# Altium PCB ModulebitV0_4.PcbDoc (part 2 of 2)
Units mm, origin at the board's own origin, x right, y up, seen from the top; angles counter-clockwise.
Board outline 60 x 54 mm, 2 copper layers (Top Layer, Bottom Layer), stack 1.671 mm thick; 125 components, 87 nets, 543 pads, 469 vias.
Unrouted connection lines stored in the file: 1.
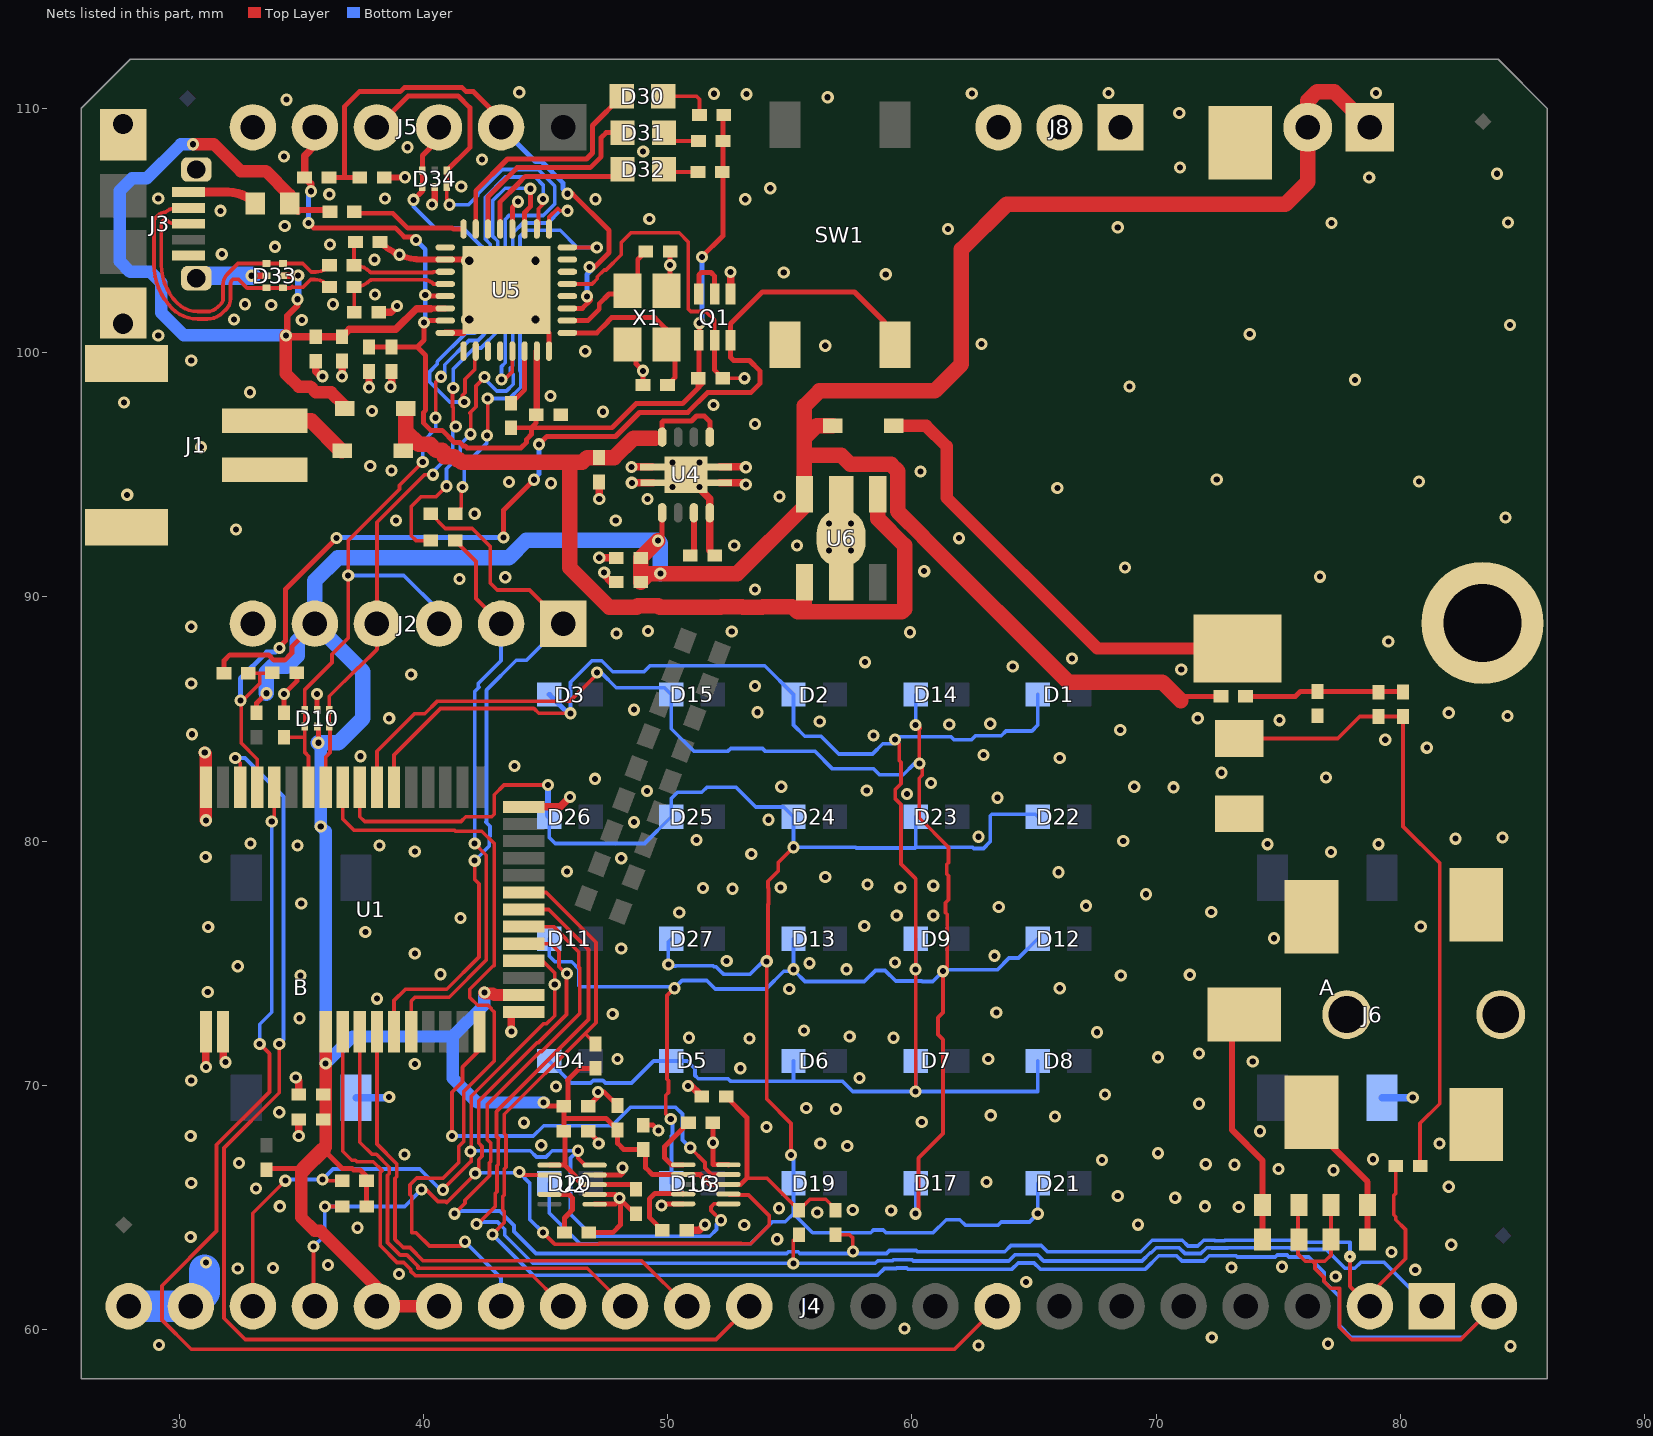
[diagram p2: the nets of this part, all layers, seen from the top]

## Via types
v1: diameter 0.5, hole 0.25, Top Layer to Bottom Layer, tented both sides, 464 vias
v2: diameter 0.66, hole 0.33, Top Layer to Bottom Layer, tented both sides, 4 vias
v3: diameter 0.5, hole 0.15, Top Layer to Bottom Layer, 1 vias

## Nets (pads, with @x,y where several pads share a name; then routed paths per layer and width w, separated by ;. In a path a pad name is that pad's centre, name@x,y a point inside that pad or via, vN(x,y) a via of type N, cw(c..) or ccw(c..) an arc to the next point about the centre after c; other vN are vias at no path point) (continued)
GND: A.2 B1.NEG B.2 C1.2 C2.2 C3.2 C4.2 C5.2 C6.2 C7.2 C8.2 C9.2 C10.2 C11.2 C12.2 C13.2 C14.2 C15.2 C16.2 C17.2 C18.2 C19.2 C20.2 C21.2 C22.2 C23.2 C24.2 C25.2 C26.2 C27.2 D10.2 D33.2 D34.2 J1.2 J1.P1 J1.P2 J2.6 J3.5 J3.H0 J3.H1 J3.H2 J3.H3 J4.21 J4.22 J5.6 J6.BARL J6.P01 J6.P02 J6.P03 J6.P04 J8.1 J8.2 J8.3 M1.BLACK M2.1 pad.2 Q1.1 R5.2 SW1.2 U1.1 U1.2 U1.13 U1.25 U1.42 U2.6 U2.7 U2.9 U3.5 U3.10 U4.4 U4.9 U5.2 U5.8 U5.16 U5.33 U6.2 X1.2 X1.4 | length 64.1
  Top Layer w0.203: R5.2@34.3,85.25 v1(34.3,86.025) 34.819,86.544 C24.2@34.819,86.893 ; D10.2@35.65,85.363 v1(35.65,86.025) ; U5.33@43.394,102.556 45.144,100.806 U5.16@45.144,100.056 ; C2.2@46.75,68.125 47.175,67.7 v1(47.175,67.625) ; C1.2@46.75,69.15 47.125,69.525 47.15,69.525 v1(47.15,69.725) 47.4,69.725 C8.2@47.95,69.175 ; C6.2@46.775,63.975 47.75,63.975 48.062,64.287 pad.2@48.062,65.337 ; U2.6@47.012,65.136 47.861,65.136 pad.2@48.062,65.337 ; U2.7@47.012,65.536 v1@47.864,65.536 ; U2.9@47.012,66.336 48.086,66.336 48.152,66.402 v1(48.152,66.628) ; C3.2@48.7,64.75 48.65,64.75 pad.2@48.062,65.337 ; X1.4@48.705,100.332 48.705,99.537 v1(48.992,99.25) C21.2@48.992,98.671 ; C9.2@49,68.375 49.4,68.375 v1(49.625,68.15) ; v1(49.752,65.078) 49.752,65.15 49.751,65.151 49.752,65.151 U3.5@50.637,65.151 ; C22.2@50.102,104.132 v1(50.102,103.575) 50.102,102.735 X1.2@50.305,102.532 ; C7.2@51.85,68.475 v1(51.85,67.653) 51.856,67.647 51.856,66.753 52.485,66.753 U3.10@52.487,66.751
  Top Layer w0.254: v1(32.963,103.143) D33.2@33.579,103.143 ; C18.2@38.225,104.525 ccw(c39.96,106.26) 39.96,103.806 U5.2@40.894,103.806 U5.33@42.144,103.806 ; C23.2@38.397,107.169 39.244,107.169 v1(39.25,107.175) ; v1(40.352,106.055) 40.462,106.165 D34.2@40.462,106.774 ; U5.8@40.894,100.806 U5.33@41.644,100.806
  Top Layer w0.305: v1(31.1,70.75) U1.1@31.1,71.699 ; U1.2@31.8,71.699 31.8,71.05 v1(31.9,70.95) ; v1(34.775,70.325) 34.9,70.2 C5.2@34.9,69.625 ; v1(34.9,67.925) C4.2@34.9,68.6 ; C25.2@35.595,99.647 35.595,99.23 35.8,99.025 v1(35.875,99.025) ; v1(36.675,99.025) C26.2@36.675,99.65 ; v1(37.775,98.575) C16.2@37.775,99.225 ; C17.2@38.175,101.65 38.675,101.65 v1(38.925,101.9) ; v1(38.65,98.6) 38.7,98.65 C19.2@38.7,99.225 ; v1(43.6,72.2) 43.599,72.999 U1.13@44.1,72.999 ; U1.25@43.8,81.399 45.599,81.399 v1(46,81.8) ; C14.2@47.193,94.699 47.193,94.007 v1(47.2,94) ; v1(47.2,91.6) 47.208,91.592 C13.2@47.895,91.592 ; v1(47.4,91) 47.4,90.9 47.698,90.602 C12.2@47.895,90.602 ; v1(48.516,95.316) U4.9@49.378,95.316 ; v1(48.534,94.666) U4.9@49.403,94.666 ; U4.9@50.749,94.991 51.724,94.016 U4.4@51.724,93.441 C15.2@51.724,91.897 ; C10.2@50.775,64.075 51.3,64.075 v1(51.525,64.3) ; v1(50.827,69.978) 50.827,70.052 50.85,70.075 50.875,70.075 C11.2@51.4,69.55 ; U4.9@52.121,94.666 53.134,94.666 v1(53.2,94.6) ; U4.9@52.121,95.316 53.184,95.316 v1(53.2,95.3) ; Q1.1@52.575,102.4 v1(52.575,103.3)
  Top Layer w0.508: v1(31.05,83.625) 31.1,83.575 U1.42@31.1,82.699 U1.42@31.1,82.199 v1(31.1,80.85)
  Bottom Layer w0.254: v1(40.352,106.055) v1@40.445,106.055
  Bottom Layer w0.305: B.2@37.25,69.5 38.575,69.5 v1(38.6,69.525) ; A.2@79.25,69.5 v1(80.5,69.5)
  Bottom Layer w0.762: J3.H3@30.709,103.041 cw(c30.954,102.796) 30.954,103.143 v1(32.963,103.143)
  Bottom Layer w1.27: J4.22@27.94,60.96 J4.21@30.48,60.96 31.05,61.53 31.05,62.45
  other v1: 84.5,59.325 62.725,59.35 29.175,59.375 77.025,59.425 72.275,59.675 59.7,60.05 64.675,61.95 77.343,62.179 39,62.275 80.6,62.45 32.4,62.5 33.85,62.525 73.075,62.55 75.15,62.575 36.1,62.65 31.1,62.75 79.625,63.175 82.075,63.475 54.483,63.703 30.475,63.8 37.3,64.175 53.137,64.287 69.25,64.3 56.125,64.8 59.15,64.875 57.578,64.903 54.559,64.973 73.375,65.025 34.125,65.05 72,65.05 48.029,65.397 70.775,65.4 68.425,65.475 33.15,65.775 81.975,65.85 30.5,66 63.05,66.05 77.25,66.525 75,66.575 73.2,66.75 72.025,66.775 32.45,66.825 67.775,66.95 78.875,66.975 39.225,67.175 70.075,67.225 57.35,67.525 44.825,67.55 56.25,67.625 81.6,67.625 30.475,67.925 74.25,68.125 54.051,68.301 44.125,68.475 60.401,68.504 65.85,68.725 63.225,68.775 34.1,68.9 56.896,69.037 55.675,69.075 71.75,69.25 67.9,69.625 45.425,69.95 30.5,70.2 57.85,70.3 52.975,70.7 39.65,70.875 73.95,70.975 47.95,71.075 63.125,71.075 70.075,71.15 71.75,71.3 53.35,71.925 50.875,71.95 59.25,71.95 57.45,72 67.575,72.175 55.575,72.25 34.925,72.75 47.75,72.925 63.453,72.979 38.1,73.55 31.175,73.825 54.975,73.95 66.05,73.975 34.975,74.5 68.55,74.5 71.375,74.525 40.7,74.55 57.325,74.75 32.4,74.875 55.803,75.004 59.303,75.029 52.415,75.098 63.378,75.304 39.65,75.4 48.1,75.6 74.825,76.025 37.625,76.275 31.191,76.479 80.825,76.5 58.05,76.525 41.525,76.85 59.375,76.95 60.875,76.95 50.475,77.075 72.25,77.1 63.553,77.304 67.125,77.35 35,77.45 69.575,77.825 52.65,78.05 51.45,78.075 54.625,78.1 59.525,78.1 60.875,78.175 58.175,78.225 56.45,78.525 66,78.725 45.875,78.75 48.1,79.3 31.09,79.35 53.425,79.475 77.15,79.55 39.65,79.575 34.85,79.825 38.2,79.825 74.55,79.875 79.1,79.875 32.925,79.9 68.65,80 51.175,80.05 82.25,80.1 84.175,80.15 62.728,80.179 48.625,80.775 54.125,80.875 63.5,81.775 59.8,81.925 49.15,82.05 58.15,82.075 70.7,82.2 54.65,82.225 69.1,82.225 60.775,82.375 47.025,82.55 76.95,82.6 72.675,82.8 43.725,83.075 66.05,83.4 37.425,83.475 62.925,83.525 81.075,83.825 79.375,84.15 58.425,84.325 30.525,84.375 68.525,84.55 61.525,84.775 63.203,84.804 56.225,84.9 75.05,84.95 38.6,85.025 71.7,85.025 84.375,85.125 81.975,85.25 53.675,85.275 48.627,85.379 53.575,86.35 30.5,86.45 39.5,86.825 71.025,87.025 64.125,87.15 58.075,87.325 66.55,87.475 79.5,88.175 47.9,88.5 59.925,88.55 52.625,88.575 49.2,88.6 30.5,88.775 53.575,90.3 41.475,90.725 43.35,90.8 76.7,90.825 60.5,91.05 68.725,91.2 56.6,91.9 57.5,91.9 52.725,92.1 55.3,92.1 61.925,92.4 32.325,92.75 56.6,93 57.5,93 38.875,93.125 47.875,93.125 84.3,93.25 42.1,93.4 49.175,94 54.575,94.1 27.875,94.175 65.95,94.45 50.2,94.5 51.3,94.5 45.225,94.65 43.5,94.7 80.75,94.725 72.475,94.8 60.35,95.125 38.7,95.175 37.825,95.35 50.2,95.5 51.3,95.5 30.9,96.125 53.575,97.075 47.35,97.575 37.9,97.6 51.875,97.85 27.75,97.95 45.2,98.225 32.9,98.375 68.91,98.603 78.13,98.882 30.5,99.675 46.625,100.05 56.45,100.275 62.85,100.35 29.15,100.7 73.825,100.75 84.475,101.125 35.025,101.325 32.25,101.35 33.775,101.95 32.7,101.975 36.3,101.975 38.025,102.375 58.925,103.2 54.75,103.275 38,103.8 39.025,104 31.75,104.025 33.925,104.325 36.175,104.425 61.475,105.05 68.425,105.125 34.325,105.175 77.175,105.3 84.4,105.325 49.251,105.461 31.7,105.8 47.05,106.275 53.175,106.275 29.15,106.3 38.425,106.3 36.15,106.475 54.2,106.725 41.55,106.8 78.715,107.163 83.947,107.315 70.968,107.569 42.4,107.9 34.3,108.025 48.997,108.229 39.35,108.4 70.942,109.804 34.4,110.35 56.55,110.45 53.225,110.575 51.892,110.592 62.45,110.6 68.05,110.625 79,110.625 43.925,110.65
  other v2: 41.877,101.355 44.594,101.356 41.877,103.755 44.594,103.756
I2C.SCL: J4.19 R2.2 U1.17 U2.2 U3.7 | length 42.4
  Top Layer w0.152: v1(35.5,63.4) 35.5,61.02 J4.19@35.56,60.96 ; v1(35.968,65.043) R2.2@36.678,65.043 ; v1(39.929,65.735) 40.113,65.735 40.602,65.246 40.905,65.246 40.952,65.2 v1@42.138,66.387 ; v1@42.263,66.511 42.263,66.961 42.404,67.102 42.404,67.498 42.263,67.639 42.263,69.366 44.637,71.74 44.695,71.74 45.856,72.901 45.856,74.327 ; v1(43.927,66.453) 43.927,66.425 44.016,66.336 U2.2@45.162,66.336 ; U1.17@44.1,75.799 U1.17@44.6,75.799 45.224,75.799 45.551,75.473 45.551,74.855 v1@45.827,74.579 ; v1(44.9,63.975) 45.35,63.525 45.352,63.525 45.38,63.496 47.17,63.496 47.198,63.525 52.998,63.525 53.002,63.521 53.398,63.521 53.679,63.802 54.154,64.277 54.154,64.673 53.311,65.516 52.522,65.516 U3.7@52.487,65.551
  Bottom Layer w0.152: v1(35.5,63.4) 35.968,63.868 v1(35.968,65.043) 39.237,65.043 v1(39.929,65.735) ; v1(42.125,66.4) 42.154,66.429 43.923,66.429 44.35,66.002 44.35,64.525 v1(44.9,63.975)
  other v1: 45.877,74.579
I2C.SDA: J4.20 R1.2 U1.16 U2.10 U3.6 | length 42.8
  Top Layer w0.152: J4.20@33.02,60.96 33.02,64.77 v1(34.35,66.1) ; v1@35.925,66.1 R1.2@36.675,66.1 ; v1(40.8,65.725) 40.8,65.752 41.927,66.879 41.954,66.879 41.958,66.883 41.958,69.558 44.921,72.521 45.045,72.521 45.377,72.853 v1(45.377,74.129) 45.377,74.598 44.876,75.099 U1.16@44.6,75.099 U1.16@44.1,75.099 ; v1(46.325,67.325) 46.325,67.025 46.614,66.736 U2.10@47.012,66.736 ; v1(52.178,64.478) 51.775,64.881 51.775,65.025 51.901,65.151 U3.6@52.487,65.151
  Bottom Layer w0.152: v1(34.35,66.1) 34.4,66.15 v1(35.875,66.15) 36.298,66.573 39.85,66.573 40.698,65.725 v1(40.8,65.725) ; v1(41.925,67.3) 41.95,67.325 44.373,67.325 44.627,67.071 45.023,67.071 45.277,67.325 v1(46.325,67.325) 46.025,67.025 46.025,64.725 46.929,63.821 51.723,63.821 52.004,64.102 52.004,64.304 v1(52.178,64.478) ; v1@45.377,73.973 v1(45.377,74.129)
IF_NRST: C23.1 J5.2 R22.2 U5.19 | length 23
  Top Layer w0.203: R22.2@36.136,107.163 36.775,107.163 ; C23.1@37.391,107.163 36.775,107.163 ; J5.2@43.18,109.22 43.18,109.545 42.05,110.675 41.753,110.675 41.572,110.856 39.233,110.856 39.052,110.675 37.375,110.675 36.775,110.075 36.775,107.163 ; v1@45.8,106.5 v1(45.9,106.5) 46.1,106.5 47.604,104.996 47.604,104.091 47.013,103.5 v1(46.8,103.5) ; U5.19@45.894,101.806 46.506,101.806 46.844,102.144 46.844,102.156 v1(46.7,102.3)
  Bottom Layer w0.203: J5.2@43.18,109.22 44.582,107.818 44.84,107.818 45.711,106.947 45.711,106.689 v1(45.9,106.5) ; v1(46.7,102.3) 46.7,103.2 47,103.5 v1(46.8,103.5)
IF_TDO: U5.12
LED_COM_GREEN: D30.K U5.31 | length 9.8
  Top Layer w0.203: U5.31@42.144,105.056 42.144,106.619 43.444,107.919 46.678,107.919 46.924,108.165 46.924,109.293 D30.K@48.121,110.49
LED_DAP_BLUE: D31.K U5.30 | length 8.4
  Top Layer w0.203: U5.30@42.644,105.056 42.644,106.369 43.839,107.564 46.826,107.564 47.28,108.018 47.28,108.798 47.481,109 D31.K@48.15,109
LED_PWR_RED: D32.K U5.29 | length 6.7
  Top Layer w0.203: U5.29@43.144,105.056 43.144,106.169 43.875,106.9 43.875,106.913 44.17,107.208 47.858,107.208 D32.K@48.15,107.5
MAG_INT1: U1.12 U3.9 | length 18
  Top Layer w0.152: v1(41.175,67.925) 41.175,69.719 41.605,70.149 41.605,70.748 42.282,71.426 42.3,71.426 U1.12@42.3,71.699 ; v1(50.925,67.45) 51.525,66.85 51.525,66.616 51.79,66.351 U3.9@52.487,66.351
  Bottom Layer w0.152: v1(41.175,67.925) 44.5,67.925 44.925,68.35 47.725,68.35 48.482,69.107 50.326,69.107 50.606,68.827 50.606,67.769 v1(50.925,67.45)
MISO: J4.14 U1.5 | length 19.6
  Top Layer w0.152: U1.5@37.4,71.699 37.4,67.675 37.895,67.18 38.076,67.18 38.607,66.649 38.607,66.383 38.536,66.312 38.536,63.571 39.049,63.058 39.324,63.058 39.783,62.599 39.783,62.527 39.799,62.512 46.708,62.512 J4.14@48.26,60.96
MOSI: J4.15 U1.4 | length 17.6
  Top Layer w0.152: U1.4@36.7,71.699 36.7,67.3 37.066,66.934 37.217,66.934 37.276,66.875 37.95,66.875 38.302,66.523 38.302,66.51 38.231,66.438 38.231,63.445 38.923,62.754 39.198,62.754 39.479,62.473 39.479,62.401 39.672,62.207 44.473,62.207 J4.15@45.465,61.215
NC1: U5.9
NC2: U5.1
NC5: U5.11
NetB1_POS1: B1.POS1 D28.2 | length 19.1
  Top Layer w0.508: D28.2@59.25,97 60.579,97 61.417,96.162 61.417,94.056 67.589,87.884 B1.POS1@73.33,87.884
NetC6_1: C6.1 U2.4 | length 2.6
  Top Layer w0.203: U2.4@45.162,65.536 45.964,65.536 46.1,65.4 46.1,64.9 45.775,64.575 C6.1@45.775,63.975
NetC7_1: C7.1 U3.1 | length 2.7
  Top Layer w0.203: U3.1@50.637,66.751 50.149,66.751 49.875,67.025 49.875,67.5 C7.1@50.85,68.475
NetC10_1: C10.1 U3.4 | length 3
  Top Layer w0.203: C10.1@49.775,64.075 49.248,64.602 49.248,65.348 49.482,65.582 50.606,65.582 U3.4@50.637,65.551
NetC27_1: C27.1 R28.1 R29.1 R37.2 | length 6.5
  Top Layer w0.203: R37.2@73.65,85.925 75.7,85.925 75.9,86.125 C27.1@76.6,86.125 80.075,86.125 R29.1@80.1,86.1
NetD30_A: D30.A R15.2 | length 2.2
  Top Layer w0.152: D30.A@49.821,110.49 51.181,110.49 51.3,110.371 R15.2@51.3,109.725
NetD31_A: D31.A R16.2 | length 1.1
  Top Layer w0.152: D31.A@50.189,108.661 R16.2@51.265,108.661
NetD32_A: D32.A R17.2 | length 1.3
  Top Layer w0.152: D32.A@49.959,107.391 R17.2@51.24,107.391
NetJ6_RING: J6.RING R31.1 R32.1 | length 5.6
  Top Layer w0.254: J6.RING@76.6,68.5 76.6,68.1 78.65,66.05 R31.1@78.65,63.7
NetJ6_TIP: J6.TIP R33.1 R34.1 | length 9.7
  Top Layer w0.254: J6.TIP@73.1,72.9 73.1,68.175 74.35,66.925 R34.1@74.35,65.1 R33.1@74.35,63.7
NetM1_RED: M1.RED R28.2 R29.2 R30.2 | length 26.4
  Top Layer w0.152: M1.RED@73.4,84.2 77.425,84.2 78.325,85.1 R29.2@80.1,85.1 80.1,80.6 81.6,79.1 81.6,69.25 80.8,68.45 R30.2@80.8,66.7
NetQ1_2: Q1.2 Q1.3 | length 2.3
  Top Layer w0.203: Q1.3@51.275,102.375 Q1.3@51.275,102.4 51.275,102.425 51.275,103.175 51.375,103.275 51.775,103.275 51.925,103.125 Q1.2@51.925,102.4 Q1.2@51.925,102.375
NR: C15.1 U4.3 | length 1.6
  Top Layer w0.254: C15.1@51.074,91.841 U4.3@51.074,93.441
NRES_FB_BL: R21.2 U5.14 | length 2.4
  Top Layer w0.203: R21.2@43.586,97.92 44.144,98.478 U5.14@44.144,100.056
P0: J4.0 R26.2 R31.2 R32.2 R33.2 R34.2 U1.20 | length 78.8
  Top Layer w0.152: v1(42.825,63.9) 43.315,64.39 43.315,64.839 43.249,64.905 43.249,65.45 43.315,65.517 43.315,66.576 43.384,66.645 43.384,67.949 43.315,68.019 43.315,68.815 46.611,72.111 ; U1.20@44.6,77.899 45.026,77.899 47.067,75.858 47.067,72.567 46.611,72.111 ; R26.2@47.041,71.696 46.626,72.111 46.611,72.111 ; 75.8,64.6 75.8,63.1 76.1,62.8 76.4,62.8 ; R32.2@77.15,65.1 R31.2@77.15,63.7 77.15,63.05 76.9,62.8 76.4,62.8 ; 77.499,61.701 77.145,61.701 76.864,61.981 76.864,62.136 76.5,62.5 76.5,62.7 76.4,62.8 ; 77.5,61.7 77.5,60.1 78,59.6 82.46,59.6 J4.0@83.82,60.96
  Bottom Layer w0.152: v1(42.825,63.9) 44.491,62.234 58.601,62.234 58.873,62.507 59.351,62.507 59.374,62.53 59.783,62.53 59.833,62.48 64.097,62.48 64.351,62.733 64.999,62.733 65.253,62.48 69.555,62.48 70.104,63.029 70.832,63.029 71.049,62.812 71.951,62.812 72.168,63.029 73.273,63.029 73.327,62.975 74.873,62.975 74.952,63.054 75.348,63.054 75.427,62.975 76.242,62.975 76.864,62.353 76.864,61.981 77.495,61.35 77.495,60.173 77.978,59.69 82.55,59.69 J4.0@83.82,60.96 J4.0@83.715,60.96
P0.16: J4.16 U1.34 | length 32.6
  Top Layer w0.152: U1.34@36.7,81.999 36.7,80.9 37.158,80.442 41.273,80.442 41.308,80.407 42.393,80.407 42.9,79.9 42.9,74.9 42.883,74.917 41.9,73.933 41.9,73.6 42.222,73.278 42.645,73.278 42.779,73.144 42.779,73.121 42.9,73 42.9,71 41.654,69.754 41.654,67.705 41.446,67.498 41.446,66.846 40.804,66.204 40.137,66.204 40.127,66.214 39.731,66.214 39.45,65.933 39.45,65.537 39.521,65.466 39.521,63.973 39.703,63.973 40.25,63.426 41.526,63.426 v1(41.7,63.6)
  Bottom Layer w0.152: v1(41.7,63.6) 43.18,62.12 J4.16@43.18,60.96
P0.18: J4.8 U1.38 | length 59.5
  Top Layer w0.152: v1(33.3,71.7) 33.7,71.3 33.7,69.731 31.537,67.568 31.537,64.037 29.3,61.8 29.3,60.4 30.5,59.2 61.74,59.2 J4.8@63.5,60.96 ; v1(33.795,80.805) 33.9,80.91 U1.38@33.9,82.199
  Bottom Layer w0.152: v1(33.3,71.7) 33.3,72.5 33.795,72.995 v1(33.795,80.805)
P0.20: J4.12 U1.40 | length 48.7
  Top Layer w0.152: v1(32.3,83.4) 32.5,83.2 U1.40@32.5,82.699 U1.40@32.5,82.199 ; v1(34.1,71.7) 34.1,69.7 31.841,67.441 31.841,60.472 32.713,59.6 51.98,59.6 J4.12@53.34,60.96
  Bottom Layer w0.152: v1(32.3,83.4) 32.7,83.4 34.274,81.826 34.274,71.874 v1(34.1,71.7)
P1: J4.1 R25.2 U1.19 | length 59.2
  Top Layer w0.152: v1@42.225,64.325 42.942,65.042 42.942,65.574 43.01,65.643 43.01,66.702 43.064,66.756 43.064,67.808 43.079,67.823 42.995,67.907 ; 42.998,67.91 42.995,67.912 42.995,68.926 46.762,72.693 46.762,75.566 45.128,77.199 U1.19@44.6,77.199 ; v1(55.143,62.713) 55.143,63.66 R25.2@55.372,63.889
  Bottom Layer w0.152: v1(42.175,64.325) 42.254,64.404 43.034,64.404 43.329,64.109 43.329,63.863 44.475,62.717 58.498,62.717 58.598,62.817 59.194,62.817 59.237,62.86 60.009,62.86 60.059,62.81 63.96,62.81 64.214,63.064 65.136,63.064 65.39,62.81 69.418,62.81 69.758,63.15 69.794,63.15 70.002,63.358 70.934,63.358 71.176,63.117 71.824,63.117 72.066,63.358 72.259,63.358 72.276,63.342 72.924,63.342 72.941,63.358 75.474,63.358 75.553,63.28 76.963,63.28 77.729,62.513 78.125,62.513 78.367,62.755 79.332,62.755 81.127,60.96 J4.1@81.28,60.96
P2: J4.2 R24.2 R30.1 U1.18 | length 64.8
  Top Layer w0.152: v1(41.275,64.75) 41.704,65.179 41.704,65.302 42.705,66.303 42.705,66.829 42.759,66.883 42.759,67.646 42.619,67.786 42.619,69.219 44.785,71.385 44.842,71.385 46.407,72.949 46.407,74.798 46.356,74.849 46.356,75.469 45.326,76.499 U1.18@44.6,76.499 U1.18@44.1,76.499 ; R24.2@56.871,63.889 57.447,63.889 57.582,63.754 v1(57.582,63.195) ; v3(77.927,62.992) 77.927,61.773 J4.2@78.74,60.96 ; J4.2@78.74,61.1 78.74,61.44 80.2,62.9 80.2,64.1 79.8,64.5 79.8,64.627 79.721,64.705 79.721,65.495 79.8,65.573 R30.1@79.8,66.7
  Bottom Layer w0.152: v1(41.275,64.75) 41.379,64.854 43.122,64.854 43.71,64.267 43.71,64.021 44.609,63.121 54.875,63.121 54.945,63.191 55.342,63.191 55.411,63.121 58.96,63.121 59.079,63.241 60.167,63.241 60.217,63.191 63.802,63.191 64.056,63.445 65.294,63.445 65.548,63.191 69.368,63.191 69.84,63.663 71.06,63.663 71.302,63.421 71.698,63.421 71.94,63.663 72.385,63.663 72.402,63.646 72.798,63.646 72.815,63.663 75.601,63.663 75.679,63.585 77.927,63.585 v3(77.927,62.992)
PRE_TGT_NRST: Q1.5 R27.2 U5.21 | length 13.8
  Top Layer w0.152: U5.21@45.894,102.806 46.906,102.806 47.121,103.021 47.121,103.098 47.402,103.379 47.479,103.379 48.1,104 48.1,104.5 48.5,104.9 50.475,104.9 50.846,104.529 50.846,101.779 50.946,101.679 51.571,101.679 51.925,101.325 Q1.5@51.925,100.5 ; R27.2@52.25,98.95 v1(53.15,98.95)
  Top Layer w0.203: Q1.5@51.925,100.5 51.925,99.275 R27.2@52.25,98.95
  Bottom Layer w0.152: v1@53.15,98.85 v1(53.15,98.95)
PRE_TGT_RXD: R36.2 U5.25 | length 20.7
  Top Layer w0.152: R36.2@40.3,92.3 39.7,92.3 39.5,92.5 39.5,93.7 39.9,94.1 40.523,94.1 v1(40.948,94.525) ; v1(41.935,96.658) 41.935,97.488 41.9,97.523 42.154,97.777 42.154,98.63 42.5,98.977 v1(42.5,99) ; U5.25@45.144,105.056 45.144,105.544 45.5,105.9 45.6,105.8 v1(45.9,105.8)
  Bottom Layer w0.152: v1(40.948,94.525) 40.948,95.239 41.2,95.492 ; 41.2,95.492 41.51,95.802 41.51,96.233 v1(41.935,96.658) ; v1@42.6,98.823 43.002,98.421 43.398,98.421 43.679,98.702 43.679,99.098 43.566,99.211 43.566,99.364 43.655,99.454 43.655,104.886 44.074,105.305 45.1,105.305 45.595,105.8 v1(45.9,105.8)
PRE_TGT_TXD: R35.2 U5.24 | length 18.1
  Top Layer w0.152: R35.2@41.3,93.4 41.55,93.65 v1@41.55,94.55 ; v1@42.632,96.6 v1(42.632,98.114) ; U5.24@45.894,104.306 45.9,104.3 v1(47.1,104.3)
  Bottom Layer w0.152: v1(41.6,94.5) 41.679,94.578 41.679,95.298 41.638,95.338 42.6,96.3 v1(42.6,96.6) ; v1(42.632,98.114) 42.486,98.114 42.484,98.116 43.524,98.116 43.983,98.575 43.983,99.224 43.96,99.248 43.96,104.76 44.2,105 45.6,105 46.3,104.3 v1(47.1,104.3)
ROW1: D1.A D2.A D3.A D4.A D5.A D6.A D7.A D8.A D9.A U1.31 | length 76.6
  Top Layer w0.152: U1.31@38.8,82.199 38.8,83.525 40.7,85.425 44.523,85.425 44.719,85.229 v1(46.027,85.229) ; v1(59.303,84.154) 59.477,83.98 59.477,83.304 59.55,83.23 59.55,82.352 59.321,82.123 59.321,81.727 59.55,81.498 59.55,79.064 60.15,78.464 v1(60.15,74.75) v1(60.15,69.75)
  Bottom Layer w0.152: D4.A@45.15,71 46.054,70.096 46.845,70.096 46.952,70.204 47.348,70.204 47.455,70.096 48.521,70.096 49.425,71 D5.A@50.15,71 50.8,71 51.121,70.679 51.121,70.405 51.255,70.271 52.474,70.271 52.57,70.175 55.15,70.175 ; v1(46.027,85.229) 46.027,86.506 46.904,87.383 47.301,87.383 47.754,86.929 49.029,86.929 49.275,87.175 53.975,87.175 D2.A@55.15,86 55.15,84.75 55.607,84.293 56.277,84.293 57.004,83.566 58.385,83.566 58.8,83.981 v1@59.206,83.981 ; D6.A@55.15,71 55.15,70.175 ; v1(59.303,84.154) 59.416,84.267 61.595,84.267 61.708,84.154 62.446,84.154 62.601,84.308 63.651,84.308 63.851,84.508 64.908,84.508 65.15,84.75 D1.A@65.15,86 ; D7.A@60.15,71 v1(60.15,69.75) ; v1(60.15,74.75) D9.A@60.15,76 ; D8.A@65.15,71 65.15,69.75 v1(60.15,69.75) ; 55.15,70.175 57.15,70.175 57.575,69.75 v1(60.15,69.75)
  Bottom Layer w0.203: D3.A@45.186,86 D3.A@45.15,86 45.921,85.229 v1(46.027,85.229)
ROW2: D11.A D12.A D13.A D14.A D15.A D16.A D17.A U1.32 | length 85.2
  Top Layer w0.152: U1.32@38.1,82.199 U1.32@38.1,82.699 38.1,83.675 39.638,85.212 40.056,85.212 40.574,85.73 46.005,85.73 v1@47.102,86.827 ; v1(50.127,68.628) 49.925,68.831 49.925,69.598 50.031,69.704 50.031,70.196 49.976,70.251 49.976,73.676 v1(50.275,73.975) ; v1(60.15,64.75) 60.266,64.866 60.266,67.022 61.27,68.027 61.27,69.27 61.275,69.275 61.275,71.874 61.067,72.082 61.067,72.774 61.275,72.983 v1(61.275,74.675) 61.449,74.849 61.449,77.006 61.374,77.081 61.374,77.477 61.5,77.603 61.5,78.573 61.421,78.652 61.421,79.048 61.5,79.127 61.5,79.75 60.296,80.954 60.296,82.573 60.425,82.702 60.425,83.2 60.303,83.322 60.303,84.597 v1@60.275,84.625
  Top Layer w0.254: v1(60.15,84.75) v1@60.275,84.625
  Bottom Layer w0.152: D11.A@45.15,76 45.15,75.3 45.393,75.057 46.075,75.057 46.356,74.777 46.356,74.094 46.415,74.035 50.215,74.035 v1(50.275,73.975) 50.592,74.292 51.603,74.292 51.95,73.945 54.028,73.945 54.754,74.671 55.204,74.671 55.625,74.25 58.047,74.25 58.505,74.707 58.901,74.707 59.337,74.271 60.405,74.271 60.426,74.25 60.85,74.25 v1(61.275,74.675) 61.337,74.737 63.498,74.737 63.974,75.213 64.363,75.213 D12.A@65.15,76 ; v1(47.102,86.904) 47.269,86.904 47.898,86.275 49.875,86.275 D15.A@50.15,86 50.15,84.6 51.067,83.683 52.474,83.683 52.578,83.787 53.883,83.787 53.987,83.683 56.024,83.683 56.751,82.956 58.436,82.956 58.674,82.719 59.644,82.719 60.104,83.179 v1(60.303,83.179) ; v1(50.127,68.628) 50.127,68.685 50.201,68.758 50.201,67.886 50.156,67.931 50.156,66.006 D16.A@50.15,66 ; v1(55.15,74.75) D13.A@55.15,76 ; v1(60.15,64.75) D17.A@60.15,66 ; v1(60.15,84.75) D14.A@60.15,86
ROW3: D19.A D20.A D21.A D22.A D23.A D24.A D25.A D26.A D27.A U1.33 | length 84.6
  Top Layer w0.152: U1.33@37.4,82.199 U1.33@37.4,81.999 37.4,81 37.6,80.8 41.539,80.8 41.739,81 42.8,81 42.9,81.1 42.9,81.9 43.3,82.3 v1(45.1,82.3) ; v1(55.05,67.15) 55.05,68.445 54.053,69.442 v1(54.053,75.079) 54.104,75.13 54.104,77.405 54.124,77.426 54.124,78.074 54.104,78.095 54.104,78.354 54.525,78.775 54.525,79.125 v1(55.15,79.75)
  Top Layer w0.254: U1.33@37.4,82.199 U1.33@37.4,82.699
  Bottom Layer w0.152: D20.A@45.15,66 45.15,64.775 46.408,63.517 53.393,63.517 54.291,64.414 54.814,64.414 55.15,64.75 ; D26.A@45.15,81 45.15,80.148 45.398,79.9 49.05,79.9 D25.A@50.15,81 50.15,81.748 50.402,82 50.998,82 51.002,81.996 51.398,81.996 51.605,82.204 52.801,82.204 53.605,81.4 54.75,81.4 D24.A@55.15,81 v1(55.15,79.75) 57.698,79.75 57.727,79.721 60.121,79.721 60.15,79.75 ; D27.A@50.15,76 50.027,75.877 v1(50.027,74.954) 50.027,74.91 50.059,74.879 50.317,74.879 50.339,74.901 51.856,74.901 51.898,74.86 51.976,74.86 52.155,74.681 52.281,74.555 53.379,74.555 53.999,75.175 54.1,75.175 54.053,75.128 v1(54.053,75.079) ; v1(55.05,67.15) 55.15,67.05 D19.A@55.15,66 55.15,64.75 ; D23.A@60.15,81 60.15,79.75 ; D21.A@65.15,66 v1(65.15,64.75) 64.81,64.41 63.656,64.41 63.518,64.271 62.193,64.271 61.961,64.504 61.402,64.504 60.865,63.967 58.935,63.967 58.823,64.079 58.427,64.079 58.315,63.967 55.933,63.967 55.15,64.75 ; D22.A@65.15,81 65.05,81.1 63.273,81.1 63.207,81.033 63.207,79.981 62.926,79.7 62.53,79.7 62.48,79.75 60.15,79.75
  Bottom Layer w0.254: v1(45.1,82.3) 45.1,81.05 D26.A@45.15,81
SCK: J4.13 U1.6 | length 21.5
  Top Layer w0.152: U1.6@38.1,71.699 38.1,67.6 38.912,66.788 38.912,66.257 38.841,66.186 38.841,63.698 39.175,63.363 39.451,63.363 39.997,62.817 48.943,62.817 J4.13@50.8,60.96
SLEEP_NREQ: U5.20
SWCLK: D10.3 D10.4 J2.3 R5.1 U1.36 U5.26 | length 38.1
  Top Layer w0.152: R5.1@34.3,84.25 35.125,84.25 ; U1.36@35.3,82.199 U1.36@35.3,82.699 35.3,83.475 35.15,83.625 D10.4@35.15,84.688 D10.3@35.15,85.363 35.15,86.202 36.262,87.313 36.262,87.648 36.921,88.308 v1(36.921,90.875) 36.928,90.881 36.928,92.309 39.019,94.4 39.019,94.567 v1(39.975,95.523) ; v1(40.502,97.33) 40.502,98.78 v1(40.727,99.005) ; U5.26@44.644,105.056 44.709,105.121 44.709,105.884 44.902,106.077 v1(44.902,106.28)
  Bottom Layer w0.152: v1(36.921,90.875) 39.2,90.875 40.64,89.435 J2.3@40.64,88.9 ; v1(39.975,95.523) 39.975,96.348 40.502,96.875 v1(40.502,97.33) ; v1@40.875,98.925 40.875,99.5 41.867,100.492 42.235,100.492 42.74,100.997 42.74,102.031 42.708,102.064 42.708,103.108 42.74,103.141 42.74,104.431 42.531,104.641 42.531,106.356 43.358,107.183 44.577,107.183 44.902,106.858 v1(44.902,106.28)
SWD_DIO: D34.3 D34.4 J5.4 U5.13 | length 25.2
  Top Layer w0.152: D34.3@40.962,106.774 40.962,106.163 v1(41.075,106.05) ; v1(43.2,98.9) 43.325,98.9 43.644,99.219 U5.13@43.644,100.056
  Top Layer w0.203: J5.4@38.1,109.22 39.38,110.5 41.425,110.5 41.9,110.025 41.9,108.387 D34.4@40.962,107.449 D34.3@40.962,106.774
  Bottom Layer w0.152: v1(41.075,106.05) 41.85,106.05 42.226,106.426 42.226,106.482 43.231,107.487 44.703,107.487 45.381,106.81 45.381,106.082 44.908,105.61 43.51,105.61 43.35,105.45 43.35,99.58 43.2,99.43 v1(43.2,98.9)
SWD_TCLK: D34.1 D34.6 J5.3 U5.10 | length 18
  Top Layer w0.152: v1(41.675,97.975) 41.598,98.052 41.598,98.247 41.704,98.352 41.704,98.904 42.104,99.304 42.104,100.016 U5.10@42.144,100.056
  Top Layer w0.203: v1(39.6,106.25) 39.962,106.612 D34.1@39.962,106.774 D34.6@39.962,107.449 39.962,108.062 40.64,108.74 J5.3@40.64,109.22
  Bottom Layer w0.152: v1(39.6,106.25) 39.6,105.975 40.475,105.1 41.619,105.1 42.404,104.315 42.425,104.315 42.436,104.305 42.436,103.268 42.403,103.235 42.403,101.792 42.436,101.759 42.436,101.124 42.108,100.796 41.74,100.796 40.57,99.626 40.57,99.525 40.248,99.203 40.248,98.807 41.08,97.975 v1(41.675,97.975)
SWDIO_RST: D10.1 D10.6 J2.4 U1.35 U5.27 | length 30.9
  Top Layer w0.152: U1.35@36,82.199 U1.35@36,82.699 36,83.446 36.179,83.625 36.179,84.659 D10.6@36.15,84.688 D10.1@36.15,85.363 36.15,85.925 37.321,87.096 37.348,87.096 38.1,87.848 J2.4@38.1,88.9 38.1,93.05 40.05,95 v1(40.4,95) ; v1(41.225,98.55) 41.196,98.521 41.196,97.777 41.225,97.748 41.225,96.825 41.324,96.924 v1(41.324,96.97)
  Top Layer w0.203: U5.27@44.144,105.056 44.144,105.731 44.379,105.966 v1(44.379,106.704)
  Bottom Layer w0.152: v1@40.498,95.221 41.206,95.929 v1@41.206,96.794 ; v1(41.225,98.55) 41.225,99.325 42.087,100.187 42.361,100.187 43.045,100.871 43.045,102.157 43.012,102.19 43.012,102.982 43.045,103.015 43.045,104.557 42.835,104.767 42.835,106.21 43.35,106.725 44.358,106.725 v1(44.379,106.704)
TARGET_SWD.NRST: C24.1 Q1.6 R23.2 SW1.1 U1.39 | length 47.3
  Top Layer w0.152: v1@32.55,85.702 32.55,84.002 33.2,83.352 U1.39@33.2,82.699 U1.39@33.2,82.199 ; v1@32.555,85.707 33.3,86.452 33.3,86.868 ; R23.2@32.837,86.868 33.3,86.868 ; C24.1@33.819,86.893 33.793,86.868 33.3,86.868
  Top Layer w0.203: v1(34.112,87.909) 34.087,87.909 34.016,87.981 34.138,87.981 34.356,88.199 34.356,90.312 v1(36.449,92.405) ; v1(43.282,92.431) 43.282,93.548 v1(44.526,94.793) ; v1(44.729,96.241) 45.053,96.564 47.867,96.564 48.847,97.544 50.093,97.544 50.099,97.55 50.749,97.55 ; 50.753,97.55 50.749,97.55 ; SW1.1@58.875,100.825 58.875,101.25 57.65,102.475 53.875,102.475 52.575,101.175 Q1.6@52.575,100.5 52.575,99.8 52.7,99.675 53.35,99.675 53.775,99.25 53.775,98.725 53.404,98.354 51.629,98.354 50.825,97.55 50.749,97.55
  Bottom Layer w0.203: v1(32.512,85.75) 32.512,86.66 33.587,87.736 33.938,87.736 v1(34.112,87.909) ; v1(36.449,92.405) 36.474,92.431 v1(43.282,92.431) ; v1(44.526,94.793) 44.526,94.818 44.729,95.021 v1(44.729,96.241)
TGT_NRESET_X: U5.22
TGT_RXD: J2.2 R36.1 U1.8 | length 23.4
  Top Layer w0.152: U1.8@39.5,72.399 39.5,73.45 39.659,73.609 41.059,73.609 42.579,75.129 42.579,79.421 v1(42.1,79.9) ; R36.1@41.3,92.3 42.154,91.446 42.154,89.926 J2.2@43.18,88.9
  Bottom Layer w0.152: v1(42.1,79.9) 42.1,86.127 42.275,86.302 42.25,86.327 42.25,86.45 43.18,87.38 J2.2@43.18,88.9
TGT_SWO: U5.28 | length 1.2
  Top Layer w0.203: U5.28@43.644,105.056 43.644,105.944 v1(43.875,106.175)
TGT_TXD: J2.1 R35.1 U1.7 | length 29.3
  Top Layer w0.152: U1.7@38.8,72.199 38.8,73.475 39.264,73.939 40.958,73.939 42.274,75.255 42.274,78.256 42.1,78.43 v1(42.1,79.2) ; R35.1@40.3,93.4 40.9,92.8 42,92.8 42.74,92.06 42.74,90.56 43.025,90.275 44.345,90.275 J2.1@45.72,88.9
  Bottom Layer w0.152: v1(42.1,79.2) 42.7,79.8 42.7,80.181 42.729,80.209 42.729,80.606 42.555,80.78 42.58,80.805 42.58,86.18 43.8,87.4 44.22,87.4 J2.1@45.72,88.9
USB_D_N: C17.1 R20.2 U5.4 | length 4.9
  Top Layer w0.152: R20.2@37.16,102.676 ccw(c37.16,103.585) 37.802,102.942 cw(c37.877,102.868) 37.877,102.973 40.015,102.973 cw(c40.015,102.403) 40.418,102.806 U5.4@40.894,102.806 ; C17.1@37.175,101.65 R20.2@37.175,102.662
USB_D_P: C18.1 R19.2 U5.3 | length 4.7
  Top Layer w0.152: C18.1@37.16,104.46 R19.2@37.16,103.575 cw(c37.16,102.667) 37.802,103.309 ccw(c37.877,103.383) 37.877,103.278 40.39,103.278 cw(c40.458,103.21) 40.458,103.306 U5.3@40.894,103.306
USB_N: D33.3 D33.4 J3.2 R20.1 | length 13.5
  Top Layer w0.152: J3.2@30.384,105.916 29.876,105.916 ccw(c29.876,105.327) 29.46,105.744 29.45,105.744 ccw(c29.45,105.292) 29.13,105.611 29.059,105.541 ccw(c29.275,105.325) 28.97,105.325 28.97,103.594 ccw(c31.494,103.594) 29.709,101.809 ccw(c30.77,102.87) 30.77,101.37 31.15,101.37 ccw(c31.15,102.279) 31.792,101.636 31.941,101.784 ccw(c31.544,102.181) 32.105,102.181 32.105,102.77 cw(c32.43,102.77) 32.2,103 32.429,103 32.786,102.643 D33.3@33.579,102.643 D33.4@34.254,102.643 34.566,102.643 34.636,102.713 34.677,102.671 35.073,102.671 35.392,102.991 35.55,102.991 cw(c35.55,102.276) 36.055,102.781 R20.1@36.16,102.676
USB_P: D33.1 D33.6 J3.3 R19.1 | length 12.5
  Top Layer w0.152: J3.3@30.384,105.266 29.876,105.266 cw(c29.876,105.856) 29.46,105.439 29.45,105.439 ccw(c29.45,105.292) 29.346,105.396 29.275,105.325 29.275,103.594 ccw(c31.494,103.594) 29.925,102.025 ccw(c30.77,102.87) 30.77,101.675 31.15,101.675 ccw(c31.15,102.279) 31.577,101.852 31.725,102 ccw(c31.544,102.181) 31.8,102.181 31.8,102.77 cw(c32.43,102.77) 31.984,103.215 ; 31.984,103.216 32.412,103.643 D33.6@34.254,103.643 35.059,103.643 35.406,103.295 35.593,103.295 ccw(c35.593,103.989) 36.084,103.499 R19.1@36.16,103.575
V3.3: C1.1 C2.1 C3.1 C4.1 C5.1 C8.1 C9.1 C11.1 C12.1 C13.1 D10.5 D28.1 J2.5 J4.17 J4.18 J7.1 J7.2 R1.1 R2.1 R3.1 R4.1 R23.1 R24.1 R25.1 R26.1 R37.1 U1.3 U1.14 U2.1 U2.8 U3.2 U3.8 U4.1 U6.5 | length 186.4
  Top Layer w0.152: 53.241,66.204 54.057,66.204 R25.1@55.372,64.889 55.824,65.341 56.468,65.341 56.871,64.939 R24.1@56.871,64.889
  Top Layer w0.2: v1(49.6,92.297) 49.774,92.472 U4.1@49.774,93.441
  Top Layer w0.203: R23.1@31.837,86.868 31.837,87.387 32.075,87.625 33.658,87.625 33.878,87.405 34.321,87.405 34.616,87.701 34.616,87.956 J2.5@35.56,88.9 ; R3.1@33.175,85.25 33.175,85.65 v1(33.575,86.05) ; R4.1@33.575,66.55 33.629,66.604 35.021,66.604 35.075,66.55 ; D10.5@35.65,84.688 35.7,84.638 v1(35.7,84.025) ; C4.1@35.9,68.6 35.9,67.375 36.671,66.604 37.08,66.604 37.139,66.545 37.405,66.545 37.675,66.275 R1.1@37.675,66.1 R2.1@37.675,65.047 ; J4.18@38.1,60.96 J4.18@38.1,61.5 ; v1(44.925,69.3) 45.075,69.15 C1.1@45.75,69.15 ; U2.1@45.162,66.736 45.789,66.736 ; C2.1@45.75,68.125 45.75,68.638 ; C2.1@45.789,68.086 45.789,66.736 ; R26.1@47.041,70.696 46.388,70.696 45.89,70.198 45.929,70.159 45.929,69.329 C1.1@45.75,69.15 ; C3.1@48.514,65.936 46.511,65.936 46.258,66.189 46.258,66.267 45.789,66.736 ; C11.1@52.375,69.55 53.241,68.684 53.241,66.204 52.988,65.951 U3.8@52.487,65.951 51.723,65.951 51.323,66.351 U3.2@50.637,66.351 49.374,66.351 49.1,66.625 49.1,67.275 C9.1@49,67.375 48.2,67.375 47.95,67.625 C8.1@47.95,68.175 47.475,68.65 47.159,68.65 47.155,68.646 45.759,68.646 45.75,68.638 ; 71.176,85.925 R37.1@72.65,85.925 ; 45.75,68.638 C1.1@45.75,69.15
  Top Layer w0.305: 69.2,86.5 69.249,86.451
  Top Layer w0.508: 35.075,66.55 35,66.475 35,66.378 35.006,66.372 35.006,65.828 35,65.822 35,64.6 35.544,64.056 35.772,64.056 38.1,61.728 38.1,61.5 38.64,60.96 J4.17@40.64,60.96 ; 35.9,67.375 36,67.475 C4.1@36,68.841 ; C4.1@35.9,68.6 ccw(c35.659,68.841) C4.1@36,68.841 ; U1.3@36,72.199 U1.3@36,71.699 v1(36,70.9) C4.1@36,68.841 ; v1(42.5,73.8) 42.539,73.761 42.845,73.761 42.906,73.699 U1.14@43.8,73.699 U1.14@44.1,73.699
  Top Layer w0.635: 35.075,66.55 35.9,67.375 ; v1(49.6,92.297) C13.1@48.895,91.592 C12.1@48.895,90.602 49.243,90.95 v1(49.7,90.95) 52.85,90.95 55.6,93.7 U6.5@55.6,94.2 55.6,95.8 ; D28.1@56.75,97 56.1,97 55.6,96.5 ; 71.001,85.75 70.252,86.5 69.2,86.5 66.4,86.5 60.487,92.413 60.487,92.426 59.42,93.494 59.42,95.145 59.145,95.42 57.48,95.42 57.1,95.8 55.6,95.8 ; J7.1@78.74,109.22 77.278,110.682 76.581,110.682 76.2,110.301 J7.2@76.2,109.22 76.2,106.985 75.286,106.07 63.881,106.07 62.027,104.216 62.027,99.517 60.935,98.425 56.21,98.425 55.6,97.815 55.6,96.5 ; 55.6,95.8 55.6,96.5
  Bottom Layer w0.508: v1(35.7,84.025) 35.8,83.925 v1(35.8,80.6) 36,80.4 v1(36,70.9) 37.1,72 41.2,72 ; v1(42.5,73.8) 42.5,73.3 41.2,72 ; v1(44.925,69.3) 42.2,69.3 41.2,70.3 41.2,72
  Bottom Layer w0.635: v1(33.575,86.05) 33.575,86.915 33.824,87.164 34.41,87.164 34.832,87.586 34.832,88.172 J2.5@35.56,88.9 ; v1(35.7,84.025) 36.525,84.025 37.52,85.02 37.52,86.94 J2.5@35.56,88.9 ; v1(49.7,90.95) 49.7,92.197 v1(49.6,92.297) 49.578,92.32 44.22,92.32 43.5,91.6 36.5,91.6 35.56,90.66 J2.5@35.56,88.9
V3.3KL: C16.1 C19.1 C20.1 J5.5 Q1.4 R15.1 R16.1 R17.1 R21.1 R22.1 R27.1 U5.5 U5.7 U5.15 | length 48.9
  Top Layer w0.203: v1(35.3,105.3) 35.5,105.1 38.847,105.1 39.215,104.732 39.568,104.732 v1(39.7,104.6) ; C16.1@37.775,100.225 C19.1@38.7,100.225 39.75,100.225 ; v1(40.077,102.355) 40.077,102.323 40.094,102.306 U5.5@40.894,102.306 ; U5.7@40.894,101.306 40.103,101.306 v1(40.027,101.23) 40.027,100.502 39.75,100.225 ; R21.1@43.586,96.92 44.42,96.92 ; C20.1@44.618,97.453 44.618,97.118 44.42,96.92 ; R27.1@51.25,98.95 51.25,98.55 ; R27.1@51.275,99.15 Q1.4@51.275,100.45 ; Q1.4@51.3,100.525 v1(51.3,101.2) ; 51.4,98.7 51.25,98.55 ; v1(51.4,103.913) 52.258,104.771 R15.1@52.258,109.535 ; 39.75,100.225 40.096,99.879 40.096,97.636 39.998,97.539 39.998,97.121 40.305,96.814 40.767,96.814 41.266,96.314 41.496,96.314 41.631,96.179 41.701,96.179 41.785,96.096 43.996,96.096 44.225,96.325 44.225,96.449 44.42,96.644 44.42,96.92 ; 44.42,96.92 47.72,96.92 48.706,97.906 50.606,97.906 51.25,98.55
  Top Layer w0.254: C20.1@44.644,97.479 U5.15@44.644,100.056
  Top Layer w0.305: v1(35.4,106.6) 35.4,106.899 R22.1@35.136,107.163 35.136,108.061 35.56,108.485 J5.5@35.56,109.22 ; C20.1@44.618,97.453 C20.1@44.644,97.479
  Bottom Layer w0.203: v1(35.3,105.3) 35.3,106.5 v1(35.4,106.6) ; v1(39.7,104.6) 40.077,104.223 v1(40.077,102.355) 40.077,101.28 v1(40.027,101.23) ; v1(51.3,101.2) 51.4,101.3 v1(51.4,103.913)
V_UNREG: C14.1 D18.1 D29.1 U4.5 U4.8 U6.1 U6.4 | length 41.7
  Top Layer w0.203: U4.8@49.774,96.541 49.774,97.157 49.806,97.189 50.241,97.189 50.247,97.195 50.602,97.195 50.973,97.195 51.178,97.4 51.5,97.4 51.724,97.176 U4.5@51.724,96.541
  Top Layer w0.635: D18.1@39.274,96.082 39.274,96.778 ; D29.1@39.274,97.707 39.274,96.778 ; 49.5,96.5 48.611,96.5 47.81,95.699 C14.1@47.193,95.699 46.699,95.699 46.5,95.5 46,95.5 ; U6.1@55.6,90.6 55.6,89.7 55.3,89.4 ; U6.4@58.6,94.2 58.6,93.2 59.7,92.1 59.7,89.5 59.58,89.38 55.32,89.38 55.3,89.4 ; 39.274,96.778 39.809,96.242 40.273,96.242 40.52,95.995 40.777,95.995 40.856,95.917 40.856,95.743 41.26,95.743 41.394,95.608 41.465,95.608 41.572,95.5 44.19,95.5 44.203,95.513 45.987,95.513 46,95.5 ; 46,95.5 46,91.185 47.604,89.58 48.731,89.58 48.776,89.625 49.624,89.625 49.669,89.58 52.181,89.58 52.201,89.6 53.049,89.6 53.069,89.58 53.873,89.58 53.893,89.6 55.1,89.6 55.3,89.4
VBATT: D18.2 J1.1 | length 2.4
  Top Layer w0.635: J1.1@34.8,97.2 35.413,97.2 36.633,95.98 D18.2@36.672,95.98
VBUS: J3.1 L1.1 | length 2.9
  Top Layer w0.381: J3.1@30.384,106.566 31.999,106.566 cw(c31.999,104.974) L1.1@33.125,106.1
VBUS_DET: R18.2 U5.32 | length 4.8
  Top Layer w0.203: R18.2@37.178,105.759 37.237,105.7 38.75,105.7 39.362,105.088 39.475,105.088 39.491,105.104 41.177,105.104 41.225,105.056 U5.32@41.644,105.056
VUSB_FILT: C25.1 C26.1 D29.2 D33.5 L1.2 R18.1 U5.6 | length 36.9
  Top Layer w0.254: D33.5@34.254,103.143 34.875,103.143 v1(34.875,103.15) ; v1@34.428,100.647 34.428,101.503 34.85,101.925 34.85,102.182 v1(34.852,102.18) ; L1.2@34.866,105.759 34.936,105.829 36.107,105.829 R18.1@36.178,105.759 ; 40.306,101.806 U5.6@40.894,101.806
  Top Layer w0.305: v1@34.428,100.647 C25.1@35.595,100.647 36.672,100.647 C26.1@36.675,100.65 36.975,100.95 38.875,100.95 39.725,101.8 40.3,101.8
  Top Layer w0.508: v1(30.575,108.525) 31.425,108.525 32.525,107.425 33.55,107.425 34.525,106.45 L1.2@34.525,106.1 ; v1(34.375,100.7) 34.375,99.125 34.9,98.6 35.372,98.6 35.603,98.369 36.226,98.369 36.774,97.821 D29.2@36.774,97.707
  Bottom Layer w0.254: v1(34.852,102.18) 34.875,102.203 v1(34.875,103.15)
  Bottom Layer w0.508: v1(30.575,108.525) 30.075,108.525 28.675,107.125 28.075,107.125 27.575,106.625 27.575,103.725 28,103.3 28.825,103.3 29.275,102.85 29.275,101.625 30.2,100.7 v1(34.375,100.7)
WAKE_NREQ: U5.23
X_IN: C21.1 U5.17 X1.1 | length 7.1
  Top Layer w0.203: U5.17@45.894,100.806 47.103,100.806 47.556,101.259 47.556,101.281 47.7,101.425 49.475,101.425 50.305,100.595 50.305,98.984 C21.1@49.992,98.671
X_OUT: C22.1 U5.18 X1.3 | length 5.2
  Top Layer w0.203: U5.18@45.894,101.306 46.731,101.306 47.2,101.775 47.2,101.997 47.599,102.396 48.569,102.396 48.775,102.602 48.775,103.805 C22.1@49.102,104.132
pads on no net: A.3 A.4 B.3 B.4 D1.0 D2.0 D3.0 D4.0 D5.0 D6.0 D7.0 D8.0 D9.0 D11.0 D12.0 D13.0 D14.0 D15.0 D16.0 D17.0 D19.0 D20.0 D21.0 D22.0 D23.0 D24.0 D25.0 D26.0 D27.0 D30.1 D31.1 D32.0 D34.5 F1.1 F2.1 F3.1 F4.1 J3.4 J3.P0 J3.P1 J5.1 SW1.3 SW1.4 U1.15 U1.41 U3.3 U4.2 U4.6 U4.7 U6.3
copper on no net: | length 2.4
  Top Layer w0.203: 40.462,107.449 40.462,107.816 v1(40.514,107.868) ; 49.749,65.951 50.637,65.951
  Top Layer w0.254: 50.424,92.524 50.424,93.441
  Bottom Layer w0.203: v1(40.514,107.868) v1@40.6,107.954

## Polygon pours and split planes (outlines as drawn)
GND on Top Layer "topgnd" (solid, pour order 0): 26,58 26,110 27,110 29,112 84,112 86,110 86,58
GND on Bottom Layer "botgnd" (solid, pour order 2): 26,58 26,110 28,112 84,112 86,110 86,58

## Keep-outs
Keep-Out Layer:
  rectangle: 24.8,62.1 30.2,91.9
  rectangle: 26.111,72.187 30.734,82.194
  lines w2: 26,58 86,58 86,110 84,112 28,112 26,110 26,58

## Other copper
Top Layer:
  pour cut-out: 46.5,112 47.5,111 47.5,110 50.346,110 50.474,110.127 50.474,110.974 51.5,112
Bottom Layer:
  pour cut-out: 47.5,110 47.5,111 46.5,112 51.5,112 50.5,111 50.5,110

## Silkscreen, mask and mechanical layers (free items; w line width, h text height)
Top Overlay:
  lines w0.152: 26.1,61.999 30.1,61.999 30.1,72.199 ; 26.1,91.999 30.1,91.999 30.1,82.2
  lines w0.203: 34.7,101.3 36.2,101.15 ; 34.775,100.7 35.05,100.7 ; 37.775,98.575 39.225,98.525 ; 38.925,100.8 cw(c39.287,100.438) 39.287,100.95 39.5,100.95 cw(c39.5,99.984) 40.183,100.667 40.375,100.475 ; 46.279,106.985 46.406,106.985 47.066,107.645 ; 76.025,66.325 cw(c76.025,65.903) 76.324,66.201 76.376,66.149 cw(c76.078,65.85) 76.5,65.85 76.5,63.906 ccw(c76.756,63.906) 76.575,63.725
  lines w0.3: 78.943,62.459 79.451,62.967
  lines w0.305: 64.845,107.026 ccw(c73.532,100.157) 67.673,90.758
  text "MKL26Z  prog" at 36.424,110.896 h1.52
  text "RESET" at 54.825,110.725 h1.52
  text "+3" at 34.366,110.693 h1.78
  text "Z" at 33.858,110.566 h2.03 r90
  text "+3" at 77.858,105.967 h2.03
  text "Z" at 61.771,105.442 h2.03
  text "+" at 33.6,97.725 h3.05
  text "-" at 83.825,94.775 h6 r90
  text "BAT" at 35.675,92.95 h1.52
  text "-" at 33.625,92.85 h3.81
  text "GND" at 85.575,91.8 h2 r90
  text "+3" at 34.112,90.602 h2.03
  text "Z" at 33.725,90.575 h2.03 r90
  text "nRF51 prog" at 37.025,85.95 h2.03
  text "V0.4" at 32.41,63.627 h3 r90
  text "P1" at 83.033,63.297 h2.5 r90
  text "P0" at 85.268,63.297 h2.5 r90
  text "P2" at 81.001,63.271 h2.5 r90
  text "22" at 27.305,58.293 h1.52
  text "21" at 29.845,58.293 h1.52
  text "20" at 32.385,58.293 h1.52
  text "19" at 34.925,58.293 h1.52
  text "18" at 37.465,58.293 h1.52
  text "17" at 40.005,58.293 h1.52
  text "16" at 42.545,58.293 h1.52
  text "15" at 45.085,58.293 h1.52
  text "14" at 47.625,58.293 h1.52
  text "13" at 50.165,58.293 h1.52
  text "12" at 52.705,58.293 h1.52
  text "11" at 55.245,58.293 h1.52
  text "10" at 57.785,58.293 h1.52
  text "9" at 60.325,58.293 h1.52
  text "8" at 62.865,58.293 h1.52
  text "7" at 65.405,58.293 h1.52
  text "6" at 67.945,58.293 h1.52
  text "5" at 70.485,58.293 h1.52
  text "4" at 73.025,58.293 h1.52
  text "3" at 75.565,58.293 h1.52
  text "P2" at 78.105,58.293 h1.52
  text "P1" at 80.645,58.293 h1.52
  text "P0" at 83.185,58.293 h1.52
Bottom Overlay:
  rectangle: 55.804,96.114 76.136,101.146
  text "Board Name" at 83.136,102.146 h5.08
  text "s/n" at 83.136,97.146 h5.08
  text "GND" at 79.425,86.925 h2.03 r270
  text "22" at 28.321,58.547 h1.52
  text "21" at 30.861,58.547 h1.52
  text "20" at 33.401,58.547 h1.52
  text "19" at 35.941,58.547 h1.52
  text "18" at 38.481,58.547 h1.52
  text "17" at 41.021,58.547 h1.52
  text "16" at 43.561,58.547 h1.52
  text "15" at 46.101,58.547 h1.52
  text "14" at 48.641,58.547 h1.52
  text "13" at 51.181,58.547 h1.52
  text "12" at 53.721,58.547 h1.52
  text "11" at 56.261,58.547 h1.52
  text "10" at 58.801,58.547 h1.52
  text "9" at 61.341,58.547 h1.52
  text "8" at 63.881,58.547 h1.52
  text "7" at 66.421,58.547 h1.52
  text "6" at 68.961,58.547 h1.52
  text "5" at 71.501,58.547 h1.52
  text "4" at 74.041,58.547 h1.52
  text "3" at 76.581,58.547 h1.52
  text "P2" at 79.451,58.547 h1.52
  text "P1" at 81.915,58.496 h1.52
  text "P0" at 84.658,58.496 h1.52
Top Solder:
  rectangle: 26,62.662 30.2,91.9
  region: 47.5,111 46.5,112 51.5,112 50.5,111
Bottom Solder:
  rectangle: 26,62 30.2,91.9
  region: 47.5,111 46.5,112 51.5,112 50.5,111
Mechanical 4:
  lines w0.152: 26,58 86,58 86,109 86,110 84,112 28,112 26,110 26,58

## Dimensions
86,58 to 77,74 on Mechanical 5
35,74 to 26,58 on Mechanical 5
56,71 to 26,58 on Mechanical 5
86,58 to 84,112 on Mechanical 5
26,58 to 86,58 on Mechanical 5
26.1,82.2 to 30.85,77.85 on Mechanical 5
30.85,77.85 to 26,58 on Mechanical 5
